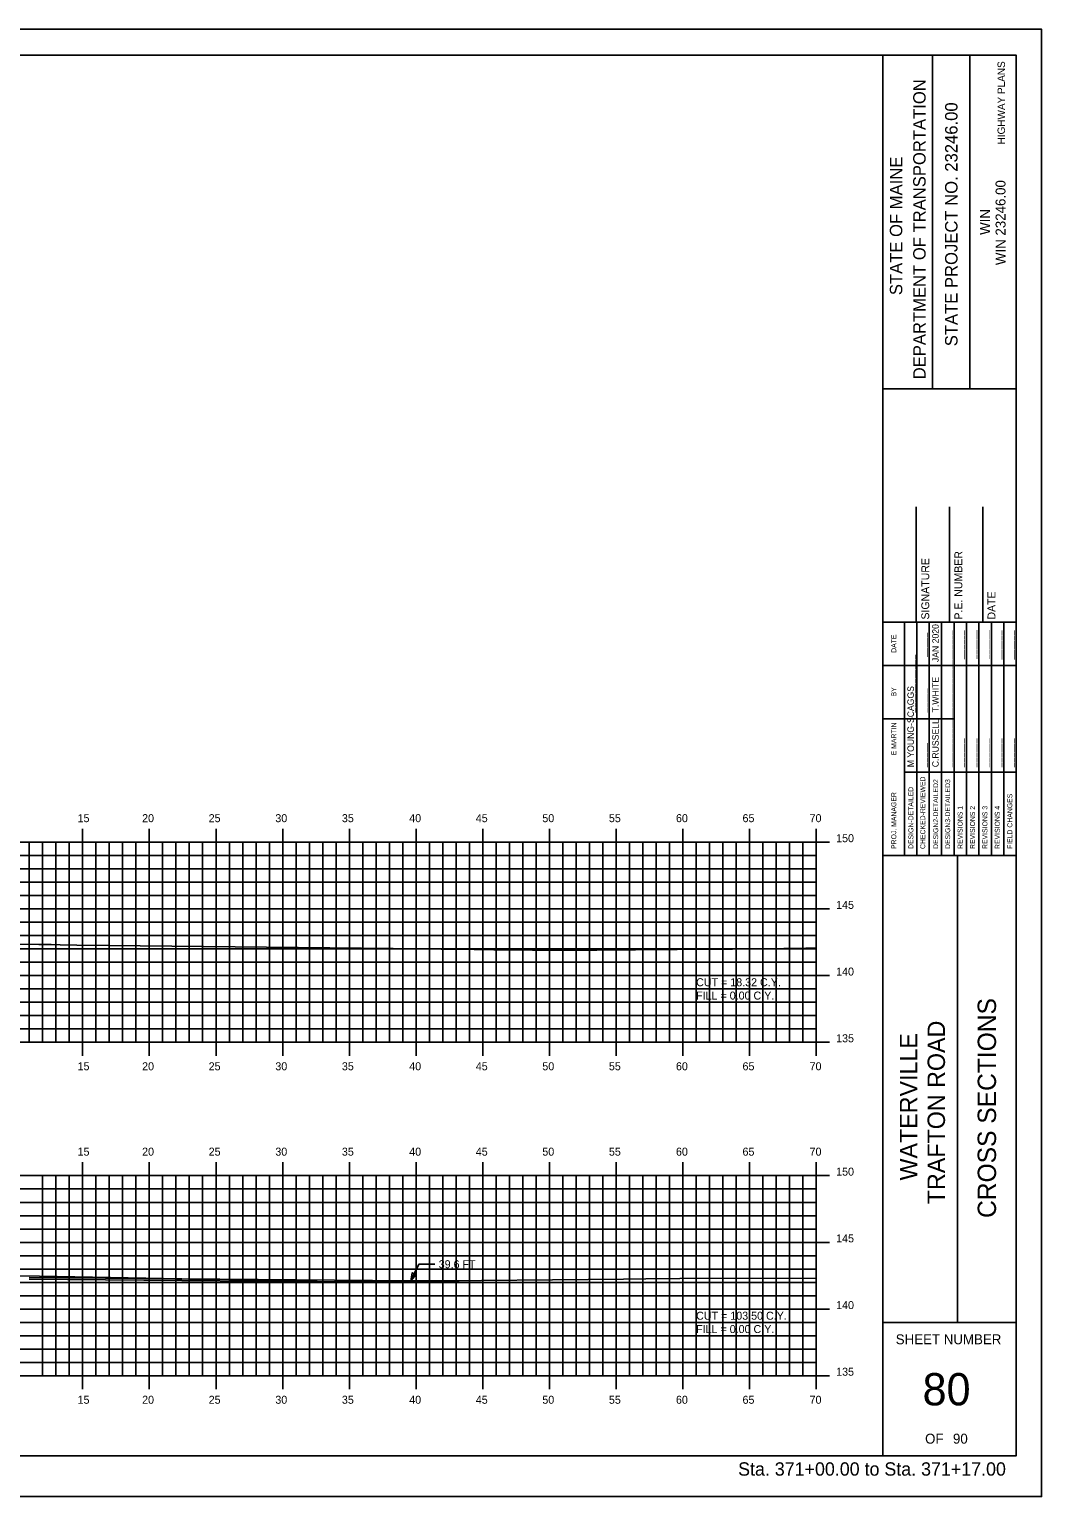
# Model space of a CAD drawing. Extents: x 1148299 to 1148469, y 608981 to 609091.
# Drawn here: x 1148392.7 to 1148468.6, y 608981.3 to 609091.3 of the extents above; entities that cross this region are included whole.
import ezdxf

# ---------------------------------------------------------------- set-up
doc = ezdxf.new("R2010")
doc.units = 0
for name, color, linetype in [('ANNOTATION', 7, 'Continuous'), ('BORDER', 7, 'Continuous'), ('D_Roadway_FinishedGrade', 7, 'Continuous'), ('D_Text_Standard', 7, 'Continuous'), ('H_V ANNOTATION', 7, 'Continuous'), ('HIGHWAY_TITLE', 7, 'Continuous'), ('MAJOR', 7, 'Continuous'), ('MINOR', 7, 'Continuous'), ('PLOT BOUNDARY', 7, 'Continuous'), ('S_Roadway_Centerline', 7, 'Continuous')]:
    doc.layers.add(name, color=color, linetype=linetype)

msp = doc.modelspace()

# ---------------------------------------------------------------- linework, layer by layer
at = {"layer": 'ANNOTATION'}
for p in [(1148421.32, 608997.45), (1148423.12, 608998.7)]:
    msp.add_line(p, (1148421.92, 608998.7), dxfattribs=at)
msp.add_lwpolyline([(1148421.72, 608997.93), (1148421.32, 608997.45), (1148421.44, 608998.06)], close=True, dxfattribs=at)
at = {"layer": 'BORDER'}
for p, q in [((1148456.72, 608984.34), (1148456.72, 609089.34)), ((1148460.45, 609064.33), (1148460.45, 609089.33)), ((1148463.25, 609064.33), (1148463.25, 609089.33)), ((1148456.72, 609064.33), (1148466.72, 609064.33)), ((1148459.22, 609046.84), (1148459.22, 609055.49)), ((1148461.72, 609046.84), (1148461.72, 609055.49)), ((1148464.22, 609046.84), (1148464.22, 609055.49)), ((1148456.72, 609046.84), (1148466.72, 609046.84)), ((1148456.72, 609029.34), (1148466.72, 609029.34)), ((1148462.31, 608994.34), (1148462.31, 609029.34)), ((1148456.72, 608994.34), (1148466.72, 608994.34))]:
    msp.add_line(p, q, dxfattribs=at)
msp.add_lwpolyline([(1148306.72, 608984.34), (1148466.72, 608984.34), (1148466.72, 609089.34), (1148306.72, 609089.34)], close=True, dxfattribs=at)
for points in [[(1148458.34, 609043.59), (1148458.34, 609046.84)], [(1148458.34, 609029.34), (1148458.34, 609046.13)], [(1148459.27, 609029.34), (1148459.27, 609046.84)], [(1148460.2, 609046.84), (1148460.2, 609029.34)], [(1148461.13, 609029.34), (1148461.13, 609046.84)], [(1148462.07, 609029.34), (1148462.07, 609046.84)], [(1148463, 609029.34), (1148463, 609046.84)], [(1148463.93, 609029.34), (1148463.93, 609046.84)], [(1148464.86, 609029.34), (1148464.86, 609046.84)], [(1148465.79, 609029.34), (1148465.79, 609046.84)], [(1148456.72, 609043.59), (1148466.72, 609043.59)], [(1148456.72, 609039.59), (1148458.34, 609039.59)], [(1148458.34, 609039.59), (1148462.07, 609039.59)], [(1148458.34, 609035.59), (1148466.72, 609035.59)]]:
    msp.add_lwpolyline(points, dxfattribs=at)
at = {"layer": 'D_Roadway_FinishedGrade'}
msp.add_line((1148392.72, 608997.71), (1148421.32, 608997.45), dxfattribs=at)
msp.add_lwpolyline([(1148421.32, 608997.45), (1148421.32, 608997.32), (1148392.72, 608997.59)], dxfattribs=at)
at = {"layer": 'MAJOR'}
for p, q in [((1148396.72, 609031.34), (1148396.72, 609030.34)), ((1148401.72, 609031.34), (1148401.72, 609030.34)), ((1148406.72, 609031.34), (1148406.72, 609030.34)), ((1148411.72, 609031.34), (1148411.72, 609030.34)), ((1148416.72, 609031.34), (1148416.72, 609030.34)), ((1148421.72, 609031.34), (1148421.72, 609030.34)), ((1148426.72, 609031.34), (1148426.72, 609030.34)), ((1148431.72, 609031.34), (1148431.72, 609030.34)), ((1148436.72, 609031.34), (1148436.72, 609030.34)), ((1148441.72, 609031.34), (1148441.72, 609030.34)), ((1148446.72, 609031.34), (1148446.72, 609030.34)), ((1148451.72, 609031.34), (1148451.72, 609030.34)), ((1148311.72, 609030.34), (1148451.72, 609030.34)), ((1148311.72, 609030.34), (1148451.72, 609030.34)), ((1148396.72, 609015.34), (1148396.72, 609030.34)), ((1148401.72, 609015.34), (1148401.72, 609030.34)), ((1148406.72, 609015.34), (1148406.72, 609030.34)), ((1148411.72, 609015.34), (1148411.72, 609030.34)), ((1148416.72, 609015.34), (1148416.72, 609030.34)), ((1148421.72, 609015.34), (1148421.72, 609030.34)), ((1148426.72, 609015.34), (1148426.72, 609030.34)), ((1148431.72, 609015.34), (1148431.72, 609030.34)), ((1148436.72, 609015.34), (1148436.72, 609030.34)), ((1148441.72, 609015.34), (1148441.72, 609030.34)), ((1148446.72, 609015.34), (1148446.72, 609030.34)), ((1148452.73, 609030.34), (1148450.72, 609030.34)), ((1148451.72, 609015.34), (1148451.72, 609030.34)), ((1148451.72, 609015.34), (1148451.72, 609030.34)), ((1148311.72, 609025.34), (1148451.72, 609025.34)), ((1148452.73, 609025.34), (1148450.72, 609025.34)), ((1148311.72, 609020.34), (1148451.72, 609020.34)), ((1148452.73, 609020.34), (1148450.72, 609020.34)), ((1148311.72, 609015.34), (1148451.72, 609015.34)), ((1148311.72, 609015.34), (1148451.72, 609015.34)), ((1148396.72, 609014.33), (1148396.72, 609015.34)), ((1148401.72, 609014.33), (1148401.72, 609015.34)), ((1148406.72, 609014.33), (1148406.72, 609015.34)), ((1148411.72, 609014.33), (1148411.72, 609015.34)), ((1148416.72, 609014.33), (1148416.72, 609015.34)), ((1148421.72, 609014.33), (1148421.72, 609015.34)), ((1148426.72, 609014.33), (1148426.72, 609015.34)), ((1148431.72, 609014.33), (1148431.72, 609015.34)), ((1148436.72, 609014.33), (1148436.72, 609015.34)), ((1148441.72, 609014.33), (1148441.72, 609015.34)), ((1148446.72, 609014.33), (1148446.72, 609015.34)), ((1148452.73, 609015.34), (1148450.72, 609015.34)), ((1148451.72, 609014.33), (1148451.72, 609015.34)), ((1148396.72, 609006.34), (1148396.72, 609005.34)), ((1148401.72, 609006.34), (1148401.72, 609005.34)), ((1148406.72, 609006.34), (1148406.72, 609005.34)), ((1148411.72, 609006.34), (1148411.72, 609005.34)), ((1148416.72, 609006.34), (1148416.72, 609005.34)), ((1148421.72, 609006.34), (1148421.72, 609005.34)), ((1148426.72, 609006.34), (1148426.72, 609005.34)), ((1148431.72, 609006.34), (1148431.72, 609005.34)), ((1148436.72, 609006.34), (1148436.72, 609005.34)), ((1148441.72, 609006.34), (1148441.72, 609005.34)), ((1148446.72, 609006.34), (1148446.72, 609005.34)), ((1148451.72, 609006.34), (1148451.72, 609005.34)), ((1148311.72, 609005.34), (1148451.72, 609005.34)), ((1148311.72, 609005.34), (1148451.72, 609005.34)), ((1148396.72, 608990.34), (1148396.72, 609005.34)), ((1148401.72, 608990.34), (1148401.72, 609005.34)), ((1148406.72, 608990.34), (1148406.72, 609005.34)), ((1148411.72, 608990.34), (1148411.72, 609005.34)), ((1148416.72, 608990.34), (1148416.72, 609005.34)), ((1148421.72, 608990.34), (1148421.72, 609005.34)), ((1148426.72, 608990.34), (1148426.72, 609005.34)), ((1148431.72, 608990.34), (1148431.72, 609005.34)), ((1148436.72, 608990.34), (1148436.72, 609005.34)), ((1148441.72, 608990.34), (1148441.72, 609005.34)), ((1148446.72, 608990.34), (1148446.72, 609005.34)), ((1148452.73, 609005.34), (1148450.72, 609005.34)), ((1148451.72, 608990.34), (1148451.72, 609005.34)), ((1148451.72, 608990.34), (1148451.72, 609005.34)), ((1148311.72, 609000.34), (1148451.72, 609000.34)), ((1148452.73, 609000.34), (1148450.72, 609000.34)), ((1148311.72, 608995.34), (1148451.72, 608995.34)), ((1148452.73, 608995.34), (1148450.72, 608995.34)), ((1148311.72, 608990.34), (1148451.72, 608990.34)), ((1148311.72, 608990.34), (1148451.72, 608990.34)), ((1148396.72, 608989.33), (1148396.72, 608990.34)), ((1148401.72, 608989.33), (1148401.72, 608990.34)), ((1148406.72, 608989.33), (1148406.72, 608990.34)), ((1148411.72, 608989.33), (1148411.72, 608990.34)), ((1148416.72, 608989.33), (1148416.72, 608990.34)), ((1148421.72, 608989.33), (1148421.72, 608990.34)), ((1148426.72, 608989.33), (1148426.72, 608990.34)), ((1148431.72, 608989.33), (1148431.72, 608990.34)), ((1148436.72, 608989.33), (1148436.72, 608990.34)), ((1148441.72, 608989.33), (1148441.72, 608990.34)), ((1148446.72, 608989.33), (1148446.72, 608990.34)), ((1148452.73, 608990.34), (1148450.72, 608990.34)), ((1148451.72, 608989.33), (1148451.72, 608990.34))]:
    msp.add_line(p, q, dxfattribs=at)
at = {"layer": 'MINOR'}
for p, q in [((1148311.72, 609029.34), (1148451.72, 609029.34)), ((1148392.72, 609015.34), (1148392.72, 609030.34)), ((1148393.72, 609015.34), (1148393.72, 609030.34)), ((1148394.72, 609015.34), (1148394.72, 609030.34)), ((1148395.72, 609015.34), (1148395.72, 609030.34)), ((1148397.72, 609015.34), (1148397.72, 609030.34)), ((1148398.72, 609015.34), (1148398.72, 609030.34)), ((1148399.72, 609015.34), (1148399.72, 609030.34)), ((1148400.72, 609015.34), (1148400.72, 609030.34)), ((1148402.72, 609015.34), (1148402.72, 609030.34)), ((1148403.72, 609015.34), (1148403.72, 609030.34)), ((1148404.72, 609015.34), (1148404.72, 609030.34)), ((1148405.72, 609015.34), (1148405.72, 609030.34)), ((1148407.72, 609015.34), (1148407.72, 609030.34)), ((1148408.72, 609015.34), (1148408.72, 609030.34)), ((1148409.72, 609015.34), (1148409.72, 609030.34)), ((1148410.72, 609015.34), (1148410.72, 609030.34)), ((1148412.72, 609015.34), (1148412.72, 609030.34)), ((1148413.72, 609015.34), (1148413.72, 609030.34)), ((1148414.72, 609015.34), (1148414.72, 609030.34)), ((1148415.72, 609015.34), (1148415.72, 609030.34)), ((1148417.72, 609015.34), (1148417.72, 609030.34)), ((1148418.72, 609015.34), (1148418.72, 609030.34)), ((1148419.72, 609015.34), (1148419.72, 609030.34)), ((1148420.72, 609015.34), (1148420.72, 609030.34)), ((1148422.72, 609015.34), (1148422.72, 609030.34)), ((1148423.72, 609015.34), (1148423.72, 609030.34)), ((1148424.72, 609015.34), (1148424.72, 609030.34)), ((1148425.72, 609015.34), (1148425.72, 609030.34)), ((1148427.72, 609015.34), (1148427.72, 609030.34)), ((1148428.72, 609015.34), (1148428.72, 609030.34)), ((1148429.72, 609015.34), (1148429.72, 609030.34)), ((1148430.72, 609015.34), (1148430.72, 609030.34)), ((1148432.72, 609015.34), (1148432.72, 609030.34)), ((1148433.72, 609015.34), (1148433.72, 609030.34)), ((1148434.72, 609015.34), (1148434.72, 609030.34)), ((1148435.72, 609015.34), (1148435.72, 609030.34)), ((1148437.72, 609015.34), (1148437.72, 609030.34)), ((1148438.72, 609015.34), (1148438.72, 609030.34)), ((1148439.72, 609015.34), (1148439.72, 609030.34)), ((1148440.72, 609015.34), (1148440.72, 609030.34)), ((1148442.72, 609015.34), (1148442.72, 609030.34)), ((1148443.72, 609015.34), (1148443.72, 609030.34)), ((1148444.72, 609015.34), (1148444.72, 609030.34)), ((1148445.72, 609015.34), (1148445.72, 609030.34)), ((1148447.72, 609015.34), (1148447.72, 609030.34)), ((1148448.72, 609015.34), (1148448.72, 609030.34)), ((1148449.72, 609015.34), (1148449.72, 609030.34)), ((1148450.72, 609015.34), (1148450.72, 609030.34)), ((1148451.72, 609029.34), (1148450.72, 609029.34)), ((1148311.72, 609028.34), (1148451.72, 609028.34)), ((1148451.72, 609028.34), (1148450.72, 609028.34)), ((1148311.72, 609027.34), (1148451.72, 609027.34)), ((1148451.72, 609027.34), (1148450.72, 609027.34)), ((1148311.72, 609026.34), (1148451.72, 609026.34)), ((1148451.72, 609026.34), (1148450.72, 609026.34)), ((1148311.72, 609024.34), (1148451.72, 609024.34)), ((1148451.72, 609024.34), (1148450.72, 609024.34)), ((1148311.72, 609023.34), (1148451.72, 609023.34)), ((1148451.72, 609023.34), (1148450.72, 609023.34)), ((1148311.72, 609022.34), (1148451.72, 609022.34)), ((1148451.72, 609022.34), (1148450.72, 609022.34)), ((1148311.72, 609021.34), (1148451.72, 609021.34)), ((1148451.72, 609021.34), (1148450.72, 609021.34)), ((1148311.72, 609019.34), (1148451.72, 609019.34)), ((1148311.72, 609018.34), (1148451.72, 609018.34)), ((1148451.72, 609019.34), (1148450.72, 609019.34)), ((1148451.72, 609018.34), (1148450.72, 609018.34)), ((1148311.72, 609017.34), (1148451.72, 609017.34)), ((1148451.72, 609017.34), (1148450.72, 609017.34)), ((1148311.72, 609016.34), (1148451.72, 609016.34)), ((1148451.72, 609016.34), (1148450.72, 609016.34)), ((1148393.72, 608990.34), (1148393.72, 609005.34)), ((1148394.72, 608990.34), (1148394.72, 609005.34)), ((1148395.72, 608990.34), (1148395.72, 609005.34)), ((1148397.72, 608990.34), (1148397.72, 609005.34)), ((1148398.72, 608990.34), (1148398.72, 609005.34)), ((1148399.72, 608990.34), (1148399.72, 609005.34)), ((1148400.72, 608990.34), (1148400.72, 609005.34)), ((1148402.72, 608990.34), (1148402.72, 609005.34)), ((1148403.72, 608990.34), (1148403.72, 609005.34)), ((1148404.72, 608990.34), (1148404.72, 609005.34)), ((1148405.72, 608990.34), (1148405.72, 609005.34)), ((1148407.72, 608990.34), (1148407.72, 609005.34)), ((1148408.72, 608990.34), (1148408.72, 609005.34)), ((1148409.72, 608990.34), (1148409.72, 609005.34)), ((1148410.72, 608990.34), (1148410.72, 609005.34)), ((1148412.72, 608990.34), (1148412.72, 609005.34)), ((1148413.72, 608990.34), (1148413.72, 609005.34)), ((1148414.72, 608990.34), (1148414.72, 609005.34)), ((1148415.72, 608990.34), (1148415.72, 609005.34)), ((1148417.72, 608990.34), (1148417.72, 609005.34)), ((1148418.72, 608990.34), (1148418.72, 609005.34)), ((1148419.72, 608990.34), (1148419.72, 609005.34)), ((1148420.72, 608990.34), (1148420.72, 609005.34)), ((1148422.72, 608990.34), (1148422.72, 609005.34)), ((1148423.72, 608990.34), (1148423.72, 609005.34)), ((1148424.72, 608990.34), (1148424.72, 609005.34)), ((1148425.72, 608990.34), (1148425.72, 609005.34)), ((1148427.72, 608990.34), (1148427.72, 609005.34)), ((1148428.72, 608990.34), (1148428.72, 609005.34)), ((1148429.72, 608990.34), (1148429.72, 609005.34)), ((1148430.72, 608990.34), (1148430.72, 609005.34)), ((1148432.72, 608990.34), (1148432.72, 609005.34)), ((1148433.72, 608990.34), (1148433.72, 609005.34)), ((1148434.72, 608990.34), (1148434.72, 609005.34)), ((1148435.72, 608990.34), (1148435.72, 609005.34)), ((1148437.72, 608990.34), (1148437.72, 609005.34)), ((1148438.72, 608990.34), (1148438.72, 609005.34)), ((1148439.72, 608990.34), (1148439.72, 609005.34)), ((1148440.72, 608990.34), (1148440.72, 609005.34)), ((1148442.72, 608990.34), (1148442.72, 609005.34)), ((1148443.72, 608990.34), (1148443.72, 609005.34)), ((1148444.72, 608990.34), (1148444.72, 609005.34)), ((1148445.72, 608990.34), (1148445.72, 609005.34)), ((1148447.72, 608990.34), (1148447.72, 609005.34)), ((1148448.72, 608990.34), (1148448.72, 609005.34)), ((1148449.72, 608990.34), (1148449.72, 609005.34)), ((1148450.72, 608990.34), (1148450.72, 609005.34)), ((1148311.72, 609004.34), (1148451.72, 609004.34)), ((1148451.72, 609004.34), (1148450.72, 609004.34)), ((1148311.72, 609003.34), (1148451.72, 609003.34)), ((1148451.72, 609003.34), (1148450.72, 609003.34)), ((1148311.72, 609002.34), (1148451.72, 609002.34)), ((1148451.72, 609002.34), (1148450.72, 609002.34)), ((1148311.72, 609001.34), (1148451.72, 609001.34)), ((1148451.72, 609001.34), (1148450.72, 609001.34)), ((1148311.72, 608999.34), (1148451.72, 608999.34)), ((1148451.72, 608999.34), (1148450.72, 608999.34)), ((1148311.72, 608998.34), (1148451.72, 608998.34)), ((1148451.72, 608998.34), (1148450.72, 608998.34)), ((1148311.72, 608997.34), (1148451.72, 608997.34)), ((1148311.72, 608996.34), (1148451.72, 608996.34)), ((1148451.72, 608997.34), (1148450.72, 608997.34)), ((1148451.72, 608996.34), (1148450.72, 608996.34)), ((1148311.72, 608994.34), (1148451.72, 608994.34)), ((1148451.72, 608994.34), (1148450.72, 608994.34)), ((1148311.72, 608993.34), (1148451.72, 608993.34)), ((1148451.72, 608993.34), (1148450.72, 608993.34)), ((1148311.72, 608992.34), (1148451.72, 608992.34)), ((1148451.72, 608992.34), (1148450.72, 608992.34)), ((1148311.72, 608991.34), (1148451.72, 608991.34)), ((1148451.72, 608991.34), (1148450.72, 608991.34))]:
    msp.add_line(p, q, dxfattribs=at)
at = {"layer": 'PLOT BOUNDARY'}
msp.add_lwpolyline([(1148298.63, 608981.28), (1148468.63, 608981.28), (1148468.63, 609091.28), (1148298.63, 609091.28)], close=True, dxfattribs=at)
at = {"layer": 'S_Roadway_Centerline'}
for points in [[(1148381.85, 609022.7), (1148393.43, 609022.67), (1148393.54, 609022.67), (1148393.57, 609022.67), (1148393.58, 609022.67), (1148393.62, 609022.66), (1148393.65, 609022.66), (1148393.7, 609022.66), (1148393.76, 609022.66), (1148393.94, 609022.66), (1148394.35, 609022.66), (1148395.04, 609022.65), (1148396.29, 609022.63), (1148422.39, 609022.34), (1148423.61, 609022.32), (1148424.1, 609022.32), (1148426.08, 609022.3), (1148427.55, 609022.28), (1148430.46, 609022.24), (1148431.54, 609022.24), (1148433.78, 609022.25), (1148435.27, 609022.25), (1148438.18, 609022.26), (1148441.3, 609022.29), (1148445.45, 609022.33), (1148447.64, 609022.35), (1148450.94, 609022.39), (1148451.72, 609022.39)], [(1148386.77, 608997.82), (1148393.49, 608997.8), (1148402.79, 608997.62), (1148404.76, 608997.59), (1148406.02, 608997.57), (1148409.36, 608997.53), (1148410.07, 608997.52), (1148411.22, 608997.49), (1148415.32, 608997.39), (1148415.37, 608997.39), (1148416.23, 608997.4), (1148416.64, 608997.41), (1148417.27, 608997.42), (1148418.21, 608997.43), (1148420.23, 608997.45), (1148421.41, 608997.45), (1148422.6, 608997.45), (1148423.4, 608997.45), (1148424.96, 608997.46), (1148426.62, 608997.47), (1148437.28, 608997.58), (1148438.96, 608997.6), (1148441.51, 608997.62), (1148451.72, 608997.65)]]:
    msp.add_lwpolyline(points, dxfattribs=at)

# ---------------------------------------------------------------- texts
at = {"layer": 'ANNOTATION'}
msp.add_text('39.6 FT', height=0.6, dxfattribs=at).set_placement((1148423.42, 608998.4))
at = {"layer": 'BORDER'}
for s, height, p in [('DEPARTMENT OF TRANSPORTATION', 0.9318, (1148459.93, 609065.04)), ('STATE PROJECT NO. 23246.00', 0.9318, (1148462.32, 609067.52)), ('STATE OF MAINE', 0.9318, (1148458.18, 609071.35)), ('WIN 23246.00', 0.7453, (1148465.92, 609073.6)), ('WIN', 0.745, (1148464.76, 609075.87)), ('SIGNATURE', 0.591, (1148460.2, 609047.03)), ('P.E. NUMBER', 0.5906, (1148462.68, 609047.03)), ('DATE', 0.591, (1148465.16, 609047.03)), ('DATE', 0.371, (1148457.73, 609044.54)), ('_____', 0.485, (1148459.94, 609044.24)), ('JAN 2020', 0.485, (1148460.91, 609043.84)), ('______', 0.485, (1148461.8, 609044.06)), ('______', 0.485, (1148462.74, 609044.06)), ('______', 0.485, (1148463.67, 609044.07)), ('______', 0.485, (1148464.6, 609044.07)), ('______', 0.485, (1148465.53, 609044.04)), ('______', 0.485, (1148466.46, 609044.04)), ('____________', 0.4845, (1148459.05, 609040.07)), ('____________', 0.4845, (1148461.8, 609040.07)), ('T.WHITE', 0.485, (1148460.91, 609040.07)), ('BY', 0.371, (1148457.73, 609041.27)), ('M YOUNG-SCAGGS', 0.4845, (1148459.05, 609035.96)), ('_____', 0.485, (1148459.98, 609040.07)), ('C.RUSSELL', 0.485, (1148460.91, 609035.96)), ('____________', 0.4845, (1148461.8, 609035.96)), ('E MARTIN', 0.373, (1148457.73, 609036.85)), ('______', 0.485, (1148462.74, 609035.96)), ('______', 0.485, (1148463.67, 609035.96)), ('______', 0.485, (1148464.6, 609035.96)), ('______', 0.485, (1148465.53, 609035.96)), ('______', 0.485, (1148466.46, 609035.96)), ('_____', 0.485, (1148459.94, 609035.96)), ('CHECKED-REVIEWED', 0.3727, (1148459.9, 609029.83)), ('DESIGN2-DETAILED2', 0.3727, (1148460.87, 609029.83)), ('DESIGN3-DETAILED3', 0.3727, (1148461.77, 609029.83)), ('PROJ. MANAGER', 0.3727, (1148457.73, 609029.83)), ('DESIGN-DETAILED', 0.3727, (1148459.01, 609029.83)), ('FIELD CHANGES', 0.3727, (1148466.43, 609029.83)), ('REVISIONS 1', 0.3727, (1148462.7, 609029.83)), ('REVISIONS 2', 0.3727, (1148463.63, 609029.83)), ('REVISIONS 3', 0.3727, (1148464.56, 609029.83)), ('REVISIONS 4', 0.3727, (1148465.49, 609029.83)), ('CROSS SECTIONS', 1.3779, (1148465.21, 609002.17))]:
    msp.add_text(s, height=height, rotation=90, dxfattribs=at).set_placement(p)
for s, height, p in [('SHEET NUMBER', 0.7453, (1148457.69, 608992.7)), ('80', 2.419, (1148459.7, 608988.12)), ('OF', 0.745, (1148459.89, 608985.25)), ('90', 0.745, (1148461.98, 608985.25))]:
    msp.add_text(s, height=height, dxfattribs=at).set_placement(p)
at = {"layer": 'D_Text_Standard'}
for s, p in [('CUT = 18.32 C.Y.', (1148442.72, 609019.54)), ('FILL = 0.00 C.Y.', (1148442.72, 609018.54)), ('CUT = 103.50 C.Y.', (1148442.72, 608994.54)), ('FILL = 0.00 C.Y.', (1148442.72, 608993.54))]:
    msp.add_text(s, height=0.6, dxfattribs=at).set_placement(p)
at = {"layer": 'H_V ANNOTATION'}
for s, height, p in [('15', 0.6, (1148396.34, 609031.84)), ('20', 0.6, (1148401.18, 609031.84)), ('25', 0.6, (1148406.17, 609031.84)), ('30', 0.6, (1148411.17, 609031.84)), ('35', 0.6, (1148416.16, 609031.84)), ('40', 0.6, (1148421.21, 609031.84)), ('45', 0.6, (1148426.2, 609031.84)), ('50', 0.6, (1148431.19, 609031.84)), ('55', 0.6, (1148436.18, 609031.84)), ('60', 0.6, (1148441.21, 609031.84)), ('65', 0.6, (1148446.2, 609031.84)), ('70', 0.6, (1148451.23, 609031.84)), ('150', 0.6, (1148453.22, 609030.34)), ('145', 0.6, (1148453.22, 609025.34)), ('140', 0.6, (1148453.22, 609020.34)), ('135', 0.6, (1148453.22, 609015.34)), ('15', 0.6, (1148396.34, 609013.24)), ('20', 0.6, (1148401.18, 609013.24)), ('25', 0.6, (1148406.17, 609013.24)), ('30', 0.6, (1148411.17, 609013.24)), ('35', 0.6, (1148416.16, 609013.24)), ('40', 0.6, (1148421.21, 609013.24)), ('45', 0.6, (1148426.2, 609013.24)), ('50', 0.6, (1148431.19, 609013.24)), ('55', 0.6, (1148436.18, 609013.24)), ('60', 0.6, (1148441.21, 609013.24)), ('65', 0.6, (1148446.2, 609013.24)), ('70', 0.6, (1148451.23, 609013.24)), ('15', 0.6, (1148396.34, 609006.84)), ('20', 0.6, (1148401.18, 609006.84)), ('25', 0.6, (1148406.17, 609006.84)), ('30', 0.6, (1148411.17, 609006.84)), ('35', 0.6, (1148416.16, 609006.84)), ('40', 0.6, (1148421.21, 609006.84)), ('45', 0.6, (1148426.2, 609006.84)), ('50', 0.6, (1148431.19, 609006.84)), ('55', 0.6, (1148436.18, 609006.84)), ('60', 0.6, (1148441.21, 609006.84)), ('65', 0.6, (1148446.2, 609006.84)), ('70', 0.6, (1148451.23, 609006.84)), ('150', 0.6, (1148453.22, 609005.34)), ('145', 0.6, (1148453.22, 609000.34)), ('140', 0.6, (1148453.22, 608995.34)), ('135', 0.6, (1148453.22, 608990.34)), ('15', 0.6, (1148396.34, 608988.24)), ('20', 0.6, (1148401.18, 608988.24)), ('25', 0.6, (1148406.17, 608988.24)), ('30', 0.6, (1148411.17, 608988.24)), ('35', 0.6, (1148416.16, 608988.24)), ('40', 0.6, (1148421.21, 608988.24)), ('45', 0.6, (1148426.2, 608988.24)), ('50', 0.6, (1148431.19, 608988.24)), ('55', 0.6, (1148436.18, 608988.24)), ('60', 0.6, (1148441.21, 608988.24)), ('65', 0.6, (1148446.2, 608988.24)), ('70', 0.6, (1148451.23, 608988.24)), ('Sta. 371+00.00 to Sta. 371+17.00', 1.0002, (1148445.87, 608982.85))]:
    msp.add_text(s, height=height, dxfattribs=at).set_placement(p)
at = {"layer": 'HIGHWAY_TITLE'}
for s, height, p in [('HIGHWAY PLANS', 0.559, (1148465.88, 609082.65)), ('TRAFTON ROAD', 1.3043, (1148461.38, 609003.2)), ('WATERVILLE', 1.304, (1148459.3, 609004.98))]:
    msp.add_text(s, height=height, rotation=90, dxfattribs=at).set_placement(p)

doc.saveas('drawing.dxf')
